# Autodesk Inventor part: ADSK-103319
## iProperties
Created: 2000-09
Part Number: ADSK-103319
Description: Hex Cap Screw
Document SubType Name: Modeling
Standard: ANSI B18.2.1 - 3/8 - 16 - 1 1/2
Designer: Administrator
Density: 1 g/cm^3
Control State: 0
Master: False
Checked Out: False
Shininess: 0.0
Density: 0.0
Volumn: 0.0
Area: 0.0
PropertySet Name: Model Information
Author: Administrator
